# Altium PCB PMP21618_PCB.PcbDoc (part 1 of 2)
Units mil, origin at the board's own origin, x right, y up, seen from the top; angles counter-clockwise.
Board outline 4330 x 1770 mil, 4 copper layers (Top Layer, Signal Layer 1, Signal Layer 2, Bottom Layer), stack 136.834 mil thick; 75 components, 40 nets, 205 pads, 71 vias.
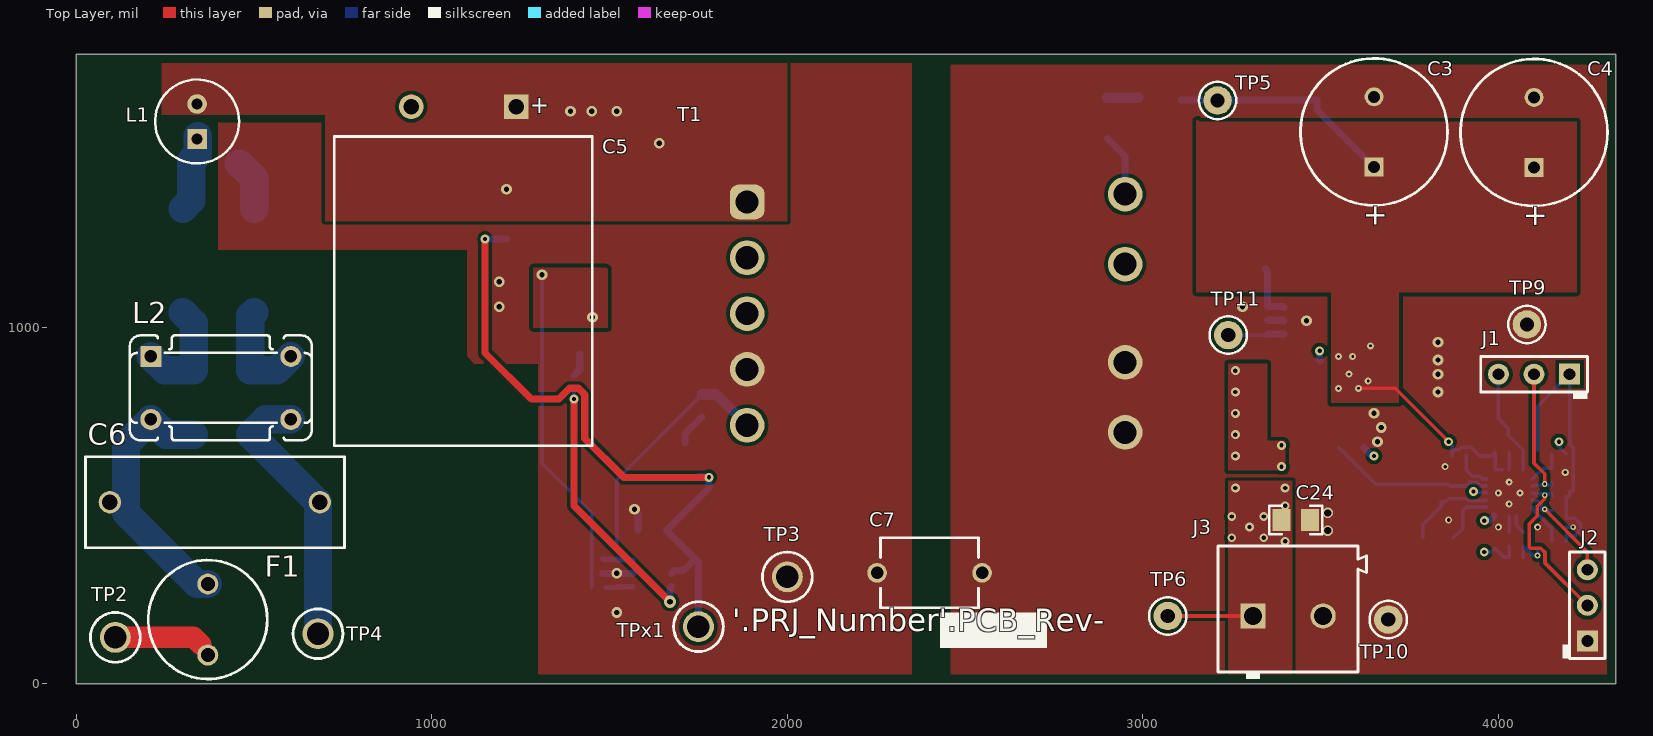
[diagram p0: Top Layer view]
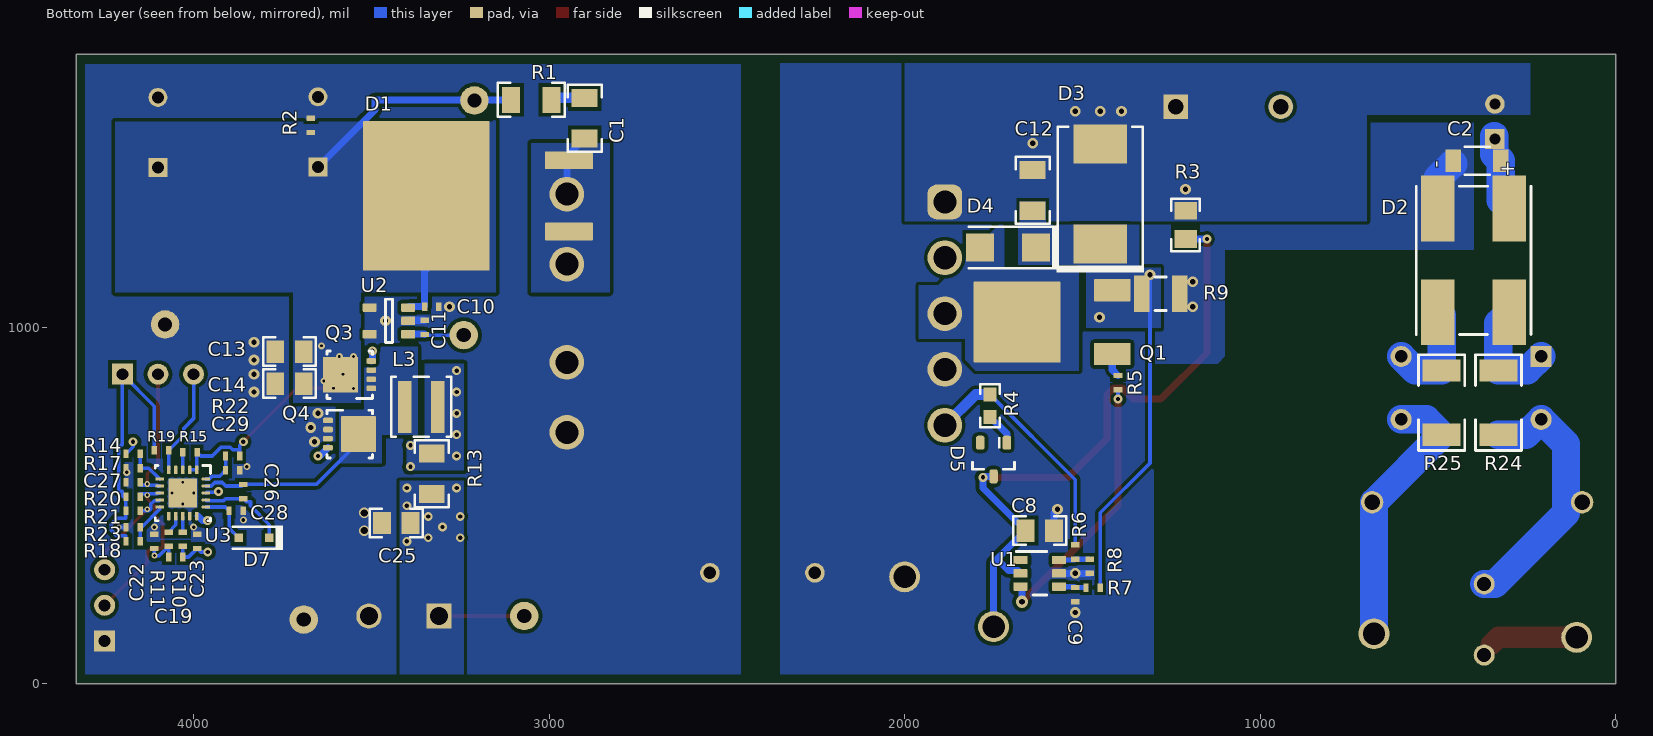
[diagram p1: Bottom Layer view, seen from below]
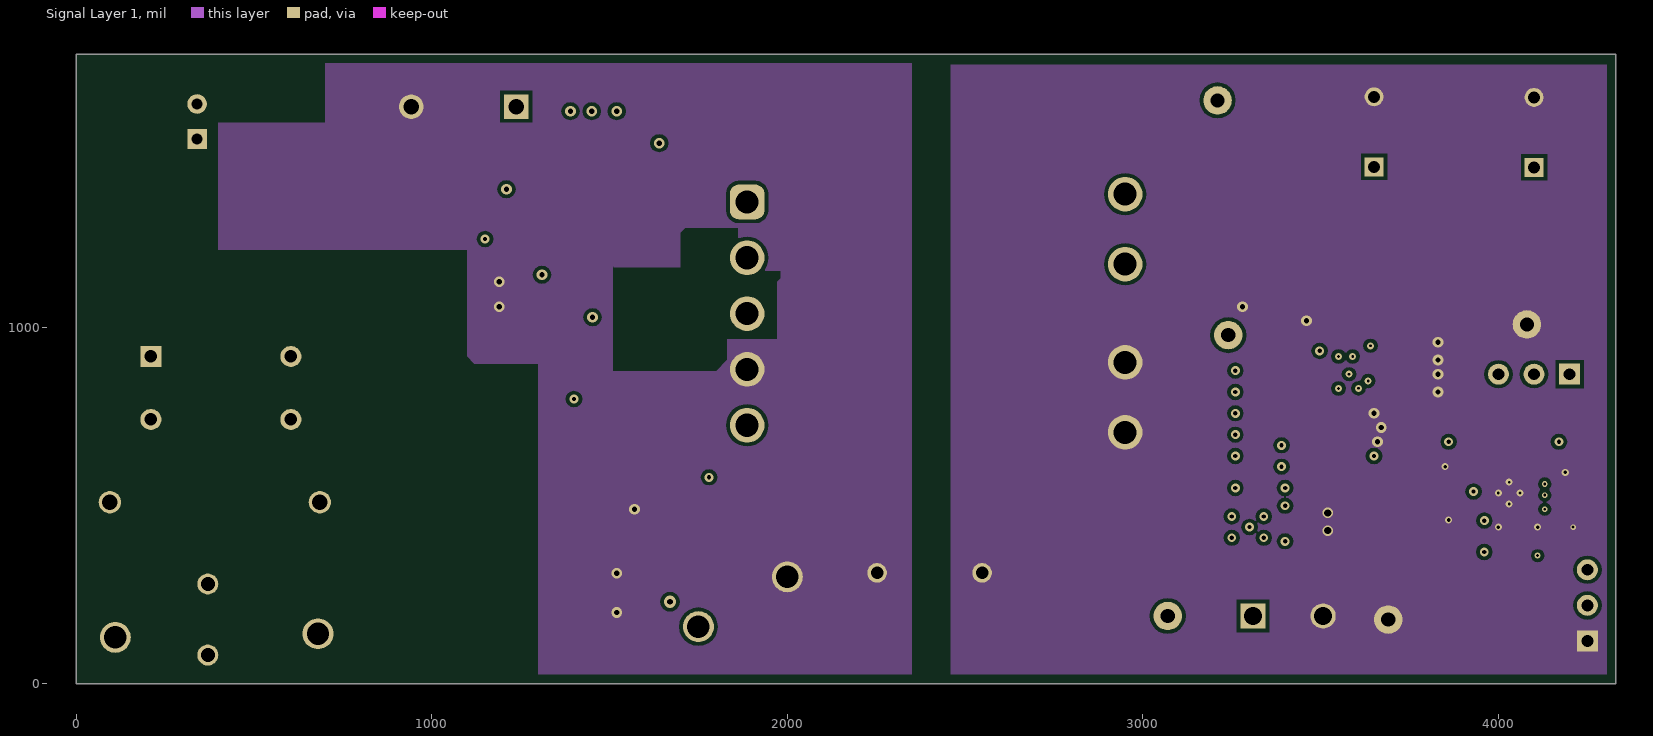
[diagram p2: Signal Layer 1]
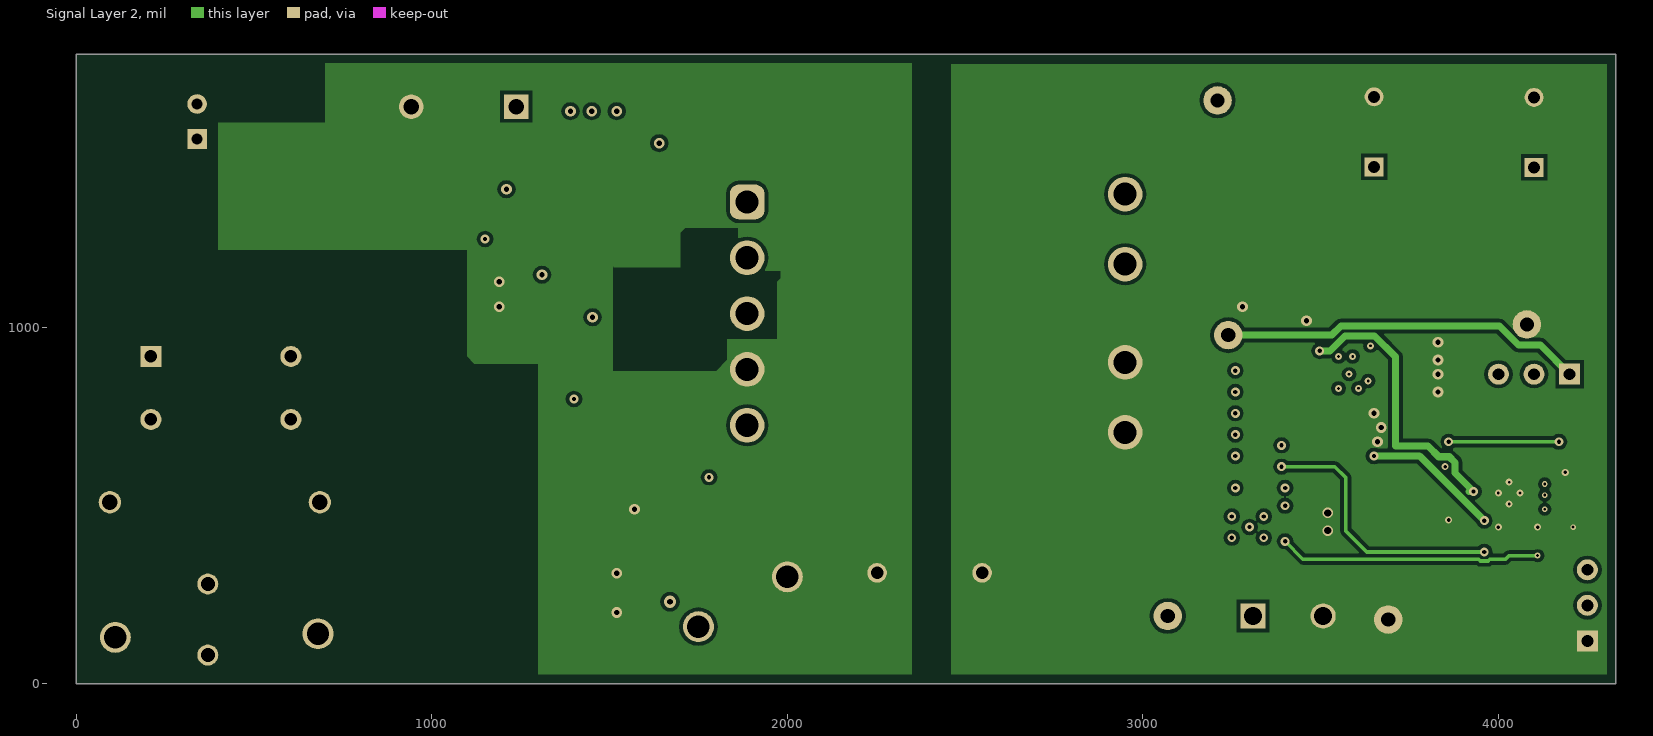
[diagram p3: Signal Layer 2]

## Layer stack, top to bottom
Top Solder: solder mask 0.4, Solder Resist, Dk 3.5
Top Layer: signal copper 2.8
Dielectric1: core 59.2, FR-4, Dk 4.8
Signal Layer 1: signal copper 1.417
Dielectric 3: core 59.2, FR-4, Dk 4.8
Signal Layer 2: signal copper 1.417
Dielectric 2: core 10, FR-4, Dk 4.8
Bottom Layer: signal copper 2.8
Bottom Solder: solder mask 0.4, Solder Resist, Dk 3.5

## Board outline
0,0 4330,0 4330,1770 0,1770

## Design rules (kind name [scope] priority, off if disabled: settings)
AcuteAngle [All] p1: minimum=4.50000000000000E+0001 checktracksonly=FALSE
AssemblyTestPointUsage [All] p1: valid=2
BoardOutlineClearance BoardOutlineClearance_MountingHoles [OnCopper and InComponentClass('Mounting Holes')] p1: gap=40 ignorepadtopadclearanceinfootprint=FALSE
BoardOutlineClearance BoardOutlineClearance_Poly [OnCopper and IsPoly] p2: gap=25 ignorepadtopadclearanceinfootprint=FALSE
BoardOutlineClearance [OnCopper and Not InComponentClass('Logo') and not InComponentClass('FiducialMark') and not InRegion(1000,500,4000,800) and not InPoly] p3: gap=75 ignorepadtopadclearanceinfootprint=FALSE
Clearance Clearance_Keepouts [((IsTrack Or IsArc) And Not InPoly) And IsFree and IsKeepOut vs ((IsTrack Or IsArc) And Not InPoly) And IsFree and IsKeepOut] p1: gap=0 ignorepadtopadclearanceinfootprint=FALSE
Clearance Clearance_Poly [InPolygon] p2: gap=10 ignorepadtopadclearanceinfootprint=FALSE except(0: Arc-Hole Track-Hole SMDPad-Hole THPad-Hole Via-Hole Fill-Hole Poly-Hole Region-Hole Text-Hole)
Clearance Clearance_FiducialMark [IsKeepOut and InComponentClass('FiducialMark') vs IsPad and InComponentClass('FiducialMark')] p3: gap=0 ignorepadtopadclearanceinfootprint=FALSE
Clearance [All] p4: gap=7.87 ignorepadtopadclearanceinfootprint=FALSE except(0: Arc-Hole Track-Hole SMDPad-Hole THPad-Hole Via-Hole Fill-Hole Poly-Hole Region-Hole Text-Hole)
ComponentClearance ComponentClearance_MountingHoles_FiducialMarks [InComponentClass('Mounting Holes') vs InComponentClass('FiducialMark')] p1: gap=50 collisioncheckmode=3 verticalgap=10 showdistances=FALSE
ComponentClearance ComponentClearance_Shunt [InComponentClass('Header') vs InComponentClass('Shunt')] p2: gap=0 collisioncheckmode=3 verticalgap=0 showdistances=FALSE
ComponentClearance ComponentClearance_Logo [InComponentClass('Logo')] p3: gap=50 collisioncheckmode=3 verticalgap=10 showdistances=FALSE
ComponentClearance ComponentClearance_ScrewToNut [(HasFootprint('NY PMS 440 0025 PH')) vs (HasFootprint('Keystone_1902C'))] p4: gap=5 collisioncheckmode=3 verticalgap=10 showdistances=FALSE
ComponentClearance ComponentClearance_MountingHoles [InComponentClass('Mounting Holes')] p5: gap=250 collisioncheckmode=3 verticalgap=100000 showdistances=FALSE
ComponentClearance ComponentClearance_SmallPassives [HasFootprint('0201*') or HasFootprint('0402*') or HasFootprint('0508') or HasFootprint('0603*') or HasFootprint('0612') or HasFootprint('0805*') or HasFootprint('0815*') or HasFootprint('0830*') or HasFootprint('1206*') or HasFootprint('1210*') or HasFootprint('1808*') or HasFootprint('1812*') or HasFootprint('1825*') or HasFootprint('2010*') or HasFootprint('2220*') or HasFootprint('2225*') or HasFootprint('2512*') or HasFootprint('2728*') or HasFootprint('3518*') vs HasFootprint('0201*') or HasFootprint('0402*') or HasFootprint('0508') or HasFootprint('0603*') or HasFootprint('0612') or HasFootprint('0805*') or HasFootprint('0815*') or HasFootprint('0830*') or HasFootprint('1206*') or HasFootprint('1210*') or HasFootprint('1808*') or HasFootprint('1812*') or HasFootprint('1825*') or HasFootprint('2010*') or HasFootprint('2220*') or HasFootprint('2225*') or HasFootprint('2512*') or HasFootprint('2728*') or HasFootprint('3518*')] p6: gap=14.96 collisioncheckmode=3 verticalgap=10 showdistances=FALSE
ComponentClearance ComponentClearance_THtoSMT [IsThruComponent vs IsSMTComponent] p7: gap=40 collisioncheckmode=3 verticalgap=30 showdistances=FALSE
ComponentClearance ComponentClearance_THtoTH [IsThruComponent vs IsThruComponent] p8: gap=30 collisioncheckmode=3 verticalgap=30 showdistances=FALSE
ComponentClearance [All] p9: gap=30 collisioncheckmode=3 verticalgap=10 showdistances=FALSE
DiffPairsRouting [All] p1: maxlimit=100 minlimit=10 mostfreqgap=10 toplayer_minwidth=15 toplayer_maxwidth=15 toplayer_prefwidth=15 midlayer1_minwidth=15 midlayer1_maxwidth=15 midlayer1_prefwidth=15 midlayer2_minwidth=15 midlayer2_maxwidth=15 midlayer2_prefwidth=15 bottomlayer_minwidth=15 bottomlayer_maxwidth=15 bottomlayer_prefwidth=15 maxuncoupledlength=1000
FabricationTestPointUsage TestPointUsage [All] p1: valid=2 allowmultiple=FALSE
FabricationTestpoint Testpoint [All] p1: side=3 testpointundercomponent=TRUE minsize=40 maxsize=100 preferedsize=60 minholesize=0 maxholesize=40 preferedholesize=32 testpointgrid=1 allowsidetop=TRUE allowsidebottom=TRUE usegrid=TRUE gridtolerance=0.01
FanoutControl Fanout_LCC [IsLCC] p1: bgadir=Out bgaviamode=Centered fanoutstyle=Auto fanoutdirection=Alternating viagrid=1 // Fanout_LCC (Default Rule)
FanoutControl Fanout_BGA [IsBGA] p2: bgadir=Out bgaviamode=Centered fanoutstyle=Auto fanoutdirection=Alternating viagrid=1 // Fanout_BGA (Default Rule)
FanoutControl Fanout_Default [All] p4: bgadir=Out bgaviamode=Centered fanoutstyle=Auto fanoutdirection=Alternating viagrid=1 // Fanout_Default (Default Rule)
FanoutControl Fanout_Small [(CompPinCount < 5)] p5: bgadir=Out bgaviamode=Centered fanoutstyle=Auto fanoutdirection=OutThenIn viagrid=1 // Fanout_Small (Default Rule)
HoleSize [All] p1: absolutevalues=TRUE maxlimit=251 minlimit=7.87 maxpercent=80.000 minpercent=20.000
MinimumAnnularRing MinimumAnnularRing_ThermalPadVias [IsVia and InAnyComponent] p1: minimumring=5.91
MinimumAnnularRing [All] p2: minimumring=3.9
MinimumSolderMaskSliver MinimumSolderMaskSliver_Logo [InComponentClass('Logo') vs InComponentClass('Logo')] p1: minsoldermaskwidth=0.7
MinimumSolderMaskSliver [All] p2: minsoldermaskwidth=0
PlaneClearance [All] p1: clearance=10
PlaneConnect [All] p1: planeconnectstyle=Direct reliefexpansion=10 reliefentries=4 reliefconductorwidth=10 reliefairgap=10
PolygonConnect [All] p1: connectstyle=Direct reliefconductorwidth=10 reliefentries=4 polygonreliefangle="90 Angle" airgapwidth=10
RoutingVias ThermalPadVias [IsVia and InAnyComponent] p1: holewidth=7.87 width=19.68 viastyle="Through Hole" minholewidth=7.87 minwidth=19.68 maxholewidth=12.99 maxwidth=23.62
RoutingVias [All] p2: holewidth=16 width=34 viastyle="Through Hole" minholewidth=8 minwidth=16 maxholewidth=40 maxwidth=65
SilkToBoardRegionClearance [Not ((IsComment or IsDesignator) And (Hide <> 'False')) and not InRegion(1000,500,4000,800)] p1:
SilkToSilkClearance SilkToSilkClearance_Pb-FreeLogo [(HasFootprint('Pb-Free_Overlay_Medium') OR HasFootprint('Pb-Free_Overlay_Small')) vs (HasFootprint('Pb-Free_Overlay_Medium') OR HasFootprint('Pb-Free_Overlay_Small'))] p1: silktosilkclearance=0
SilkToSilkClearance [All] p2: silktosilkclearance=4
SilkToSolderMaskClearance SilkToComponentPadClearance [(IsPad or IsFill or IsRegion) and InAnycomponent] p1: minsilkscreentomaskgap=5 clearancetoexposedcopper=TRUE
SilkToSolderMaskClearance "Silk to Solder Mask Opening" [All] p2: minsilkscreentomaskgap=0.1 clearancetoexposedcopper=TRUE
SolderMaskExpansion [All] p1: expansion=1.97
Width [All] p1: maxlimit=100 minlimit=6 preferedwidth=10 checkconnectedcopper=TRUE
14 further rules are at their usual default settings.

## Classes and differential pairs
component class BQ24725Z: C10 C11 C13 C14 C19 C22 C23 C24 C25 C26 C27 C28 C29 D7 J1 J2 J3 L3 Q3 Q4 R10 R11 R13 R14 R15 R17 R18 R19 R20 R21 R22 R23 TP5 TP6 TP9 TP10 TP11 U2 U3
component class Header: J1 J2
component class PMP21618_BlankSheet: C1 C2 C3 C4 C5 C6 C7 C8 C9 C12 D1 D2 D3 D4 D5 F1 L1 L2 Q1 R1 R2 R3 R4 R5 R6 R7 R8 R9 R24 R25 T1 TP2 TP3 TP4 TPx1 U1

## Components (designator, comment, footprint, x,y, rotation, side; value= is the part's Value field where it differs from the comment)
C1 "Capacitor" 1206 2900,1590 r270 bottom value=330pF
C2 "Capacitor" 1206_190 390,1470 r0 bottom value=0.1uF
C3 "Cap_Polarized" Chemi-Con_1000x1600 3650,1551.57 r90 top value=330uF
C4 "Cap_Polarized" Chemi-Con_1000x1600 4100,1550 r90 top value=330uF
C5 "EEU-EE2G470S" EE_1800x2000_HorizontalUp 1090,1150 r180 top value=47uF
C6 "890324025017" WCAP-FTX2_1800x600x1200 390,510 r0 top value=0.1uF
C7 "DE2E3KY152MN3AM02F" KY_700x500x1000 2400,311.49 r180 top value=1500pF
C8 "Capacitor" 0805_HV 1620,430 r180 bottom value=4.7uF
C9 "Capacitor" 0402S 1520,250 r270 bottom value=100pF
C10 "Capacitor" 0402S 3330,1060 r180 bottom value=2.2uF
C11 "Capacitor" 0402S 3350.31,1001.81 r90 bottom value=2.2uF
C12 "Capacitor" 1206 1640,1387.09 r270 bottom value=1000pF
C13 "Capacitor" 0805_HV 3729.99,933.66 r180 bottom value=10uF
C14 "Capacitor" 0805_HV 3729.99,843.66 r180 bottom value=10uF
C19 "Capacitor" 0402S 4050.16,355.91 r180 bottom value=0.1uF
C22 "Capacitor" 0402S 4110,400 r270 bottom value=0.1uF
C23 "Capacitor" 0402S 3990,400 r270 bottom value=0.1uF
C24 "Capacitor" 0805_HV 3430,460 r180 top value=10uF
C25 "Capacitor" 0805_HV 3430,451.49 r180 bottom value=10uF
C26 "Capacitor" 0402S 3860,540 r270 bottom value=0.047uF
C27 "Capacitor" 0402S 4170.16,565.91 r0 bottom value=100pF
C28 "Capacitor" 0402S 3880.16,485.91 r180 bottom value=1uF
C29 "Capacitor" 0402S 3890,600 r180 bottom value=1uF
D1 "MBRB20200CTT4G" DDPAK 3190,1371.49 r0 bottom value=200V
D2 "DIODE_BRIDGE_Pos1_Neg4_AC23" Z4-D 400,1190 r270 bottom value=600V
D3 "Diode_TVS_Uni" SMC 1450,1376.49 r90 bottom value=150V
D4 "DIODE" SMA 1710,1226.49 r0 bottom value=600V
D5 "DIODE_A1C3" SOT-23 1750,630 r270 bottom value=200V
D7 "DIODE_SCHOTTKY" SOD-323 3830,410 r0 bottom value=30V
F1 "Fuse" FUSE_372 370,180 r270 top
J1 "Header_3x1" Mill-Max_800-10-003-10-001000 4100,870 r180 top
J2 "Header_3x1" Mill-Max_800-10-003-10-001000 4250,220 r90 top
J3 "691 101 710 002" Wurth_691101710002 3408.43,190 r0 top
L1 "Inductor_Iron" WE-TI_5075 340,1580.79 r90 top value=22uH
L2 "INDUCTOR_COUPLED_12_43" WE-CMB_XS 406.85,831.42 r0 top value=1mH
L3 "Inductor_Iron" XAL4030 3360,777.99 r180 bottom value=4.7uH
Q1 "IPD60R950C6ATMA1" DPAK 1550,1016.49 r0 bottom value=600V
Q3 "MOSFET_N_D56789G4S123" DNH0008A 3561.02,868.7 r0 bottom value=30V
Q4 "MOSFET_N_D56789G4S123" DNH0008A 3561.02,701.61 r180 bottom value=30V
R1 "Resistor" 1206 3050,1641.49 r0 bottom value=20
R2 "Resistor" 0402S 3670,1570 r270 bottom value=10.0k
R3 "Resistor" 0805_HV 1210,1290 r90 bottom value=1.5Meg
R4 "Resistor" 0603 1760,781.49 r90 bottom value=0
R5 "Resistor" 0402S 1400,846.49 r90 bottom value=0
R6 "Resistor" 0402S 1520,370 r90 bottom value=110k
R7 "Resistor" 0402S 1470,270 r180 bottom value=681
R8 "Resistor" 0402S 1480,330 r90 bottom value=33.2k
R9 "Resistor" 1210L 1280,1096.49 r0 bottom value=0.27
R10 "Resistor" 0402S 4030.16,405.91 r270 bottom value=10
R11 "Resistor" 0402S 4070.16,405.91 r270 bottom value=7.5
R13 "Resistor" 1206 3330,590 r270 bottom value=0.01
R14 "Resistor" 0402S 4170.16,645.91 r0 bottom value=430k
R15 "Resistor" 0402S 4010,650 r180 bottom value=4.02k
R17 "Resistor" 0402S 4170.16,605.91 r180 bottom value=82.5k
R18 "Resistor" 0402S 4170,400 r0 bottom value=316k
R19 "Resistor" 0402S 4090.16,655.91 r180 bottom value=10.0k
R20 "Resistor" 0402S 4170.16,525.91 r180 bottom value=10.0k
R21 "Resistor" 0402S 4170.16,485.91 r180 bottom value=10.0k
R22 "Resistor" 0402S 3890,640 r0 bottom value=10
R23 "Resistor" 0402S 4170,440 r180 bottom value=100k
R24 "Resistor" 2010 330,790 r90 bottom value=0
R25 "Resistor" 2010 490,790 r90 bottom value=0
T1 "RLTI-1298" Renco_RLTI-1298 2410,1041.49 r0 top value=220uH
TP2 "5012" Keystone5012 110,130 r90 top
TP3 "5011" Keystone5011 2000,300 r0 top
TP4 "5012" Keystone5012 680,140 r90 top
TP5 "5000" Keystone5000 3210,1640 r180 top
TP6 "5000" Keystone5000 3070,190 r180 top
TP9 "5001" Keystone5001 4080,1010 r180 top
TP10 "5001" Keystone5001 3690,180 r90 top
TP11 "5000" Keystone5000 3240,980 r90 top
TPx1 "5010" Keystone5010 1750,160 r0 top
U1 "UCC28704DBVR-1" DBV0006A_N 1620,310 r180 bottom
U2 "TI-TLV7013XDBV5" DBV0005A_N 3450.31,1020 r0 bottom
U3 "BQ24725ARGRT" RGR0020A 4030.16,535.91 r270 bottom

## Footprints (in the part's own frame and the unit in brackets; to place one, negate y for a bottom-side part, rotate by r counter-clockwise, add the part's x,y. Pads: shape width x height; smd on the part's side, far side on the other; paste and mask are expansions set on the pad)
0402S [mil] "Based on C0402S footprint from PADS legacy"
  rect 15x24 smd: 1(-20,0) 2(20,0)
  body extent -22,-12 22,12, height 24
0603 [mm] "0603 from SM-752 data"
  rect 1x0.95 smd: 1(-0.8,0) 2(0.8,0)
  silkscreen extent -1.52,-0.69 1.52,0.69, body extent -0.87,-0.47 0.87,0.47, height 1
0805_HV [mil] "0805 with 30mil clearance between pads"
  rect 50x63 smd: 1(-40,0) 2(40,0)
  silkscreen extent -74,-40 74,40, body extent -43,-29 43,29, height 57
1206 [mm] "1206 from SM-752 data"
  rect 1.3x1.85 smd: 1(-1.45,0) 2(1.45,0)
  silkscreen extent -2.4,-1.21 2.4,1.21, body extent -1.7,-0.9 1.7,0.9, height 1.35
1206_190 [mm] "1206_190"
  rect 1.1x1.6 smd: 1(-1.7,0) 2(1.7,0)
  silkscreen extent -0.9,-1 0.9,1, body extent -1.75,-0.95 1.75,0.95, height 1.9
1210L [mm] "1210 from SM-752 data"
  rect 1.1x2.6 smd: 1(-1.35,0) 2(1.35,0)
  silkscreen extent -0.4,-1.2 0.4,1.2, body extent -1.7,-1.35 1.7,1.35, height 1.35
2010 [mm] "Chip Capacitor, Body 5.08x2.54mm, IPC Medium Density"
  rect 1.6x2.7 smd: 1(-2.3,0) 2(2.3,0)
  silkscreen extent -3.42,-1.65 3.42,1.65, body extent -2.73,-1.45 2.73,1.45, height 1.66
Chemi-Con_1000x1600 [mm] "TH, 2-Leads, Dia 10mm, Pin Spacing 5mm"
  rect 1.35x1.35 hole 0.85: 1(-2.5,0)
  round 1.35 hole 0.85: 2(2.5,0)
  silkscreen extent -5.25,-5.25 5.25,5.25, body extent -5.25,-5.25 5.26,5.25, height 17.5
DBV0005A_N [mm] "SOT23, 5-Leads, Body 2.9x1.6mm, Pitch 0.95mm, Lead Span 2.8mm, IPC Medium Density"
  rrect17% 1x0.6 smd: 1(-1.375,0.95) 2(-1.375,0) 3(-1.375,-0.95) 4(1.375,-0.95) 5(1.375,0.95)
  silkscreen extent -0.25,-1.55 0.25,1.55, body extent -1.42,-1.46 1.42,1.46, height 1.09
DBV0006A_N [mm] "SOT23, 6-Leads, Body 2.9x1.6mm, Pitch 0.95mm, Lead Span 2.8mm, IPC Medium Density"
  rrect17% 1x0.6 smd: 1(-1.375,0.95) 2(-1.375,0) 3(-1.375,-0.95) 4(1.375,-0.95) 5(1.375,0) 6(1.375,0.95)
  silkscreen extent -1.68,-1.55 0.5,1.55, body extent -1.42,-1.46 1.42,1.46, height 1.12
DDPAK [mil] "D2-PAK, 3-Pads, Body 9.7x10.4mm (max), TO-263AB, using Vishay Silionix recommended pad sizes"
  rrect8% 135x49.49 smd: 1(-246.06,100) 3(-246.06,-100)
  rrect1% 355x420 smd paste-181.1: 2(155.51,0)
  body extent -295,-202 324,202, height 180
DNH0008A [mm] "VSONP-8"
  rrect50% 0.7x0.4 smd paste-0.05 mask-0.05: 1(-1.55,0.975) 2(-1.55,0.325) 3(-1.55,-0.325) 4(-1.55,-0.975) 5(1.55,-0.975) 6(1.55,-0.325) 7(1.55,0.325) 8(1.55,0.975)
  rrect4% 2.51x2.55 smd paste-1.5 mask-1.5: 9(0.645,0)
  rrect14% 0.705x1.125 on Bottom Paste: 9A(-0.208,0.662) 9B(0.697,0.662) 9C(-0.208,-0.663) 9D(0.697,-0.663)
  silkscreen extent -1.62,-1.7 1.62,1.7, body extent -1.65,-1.65 1.65,1.65, height 0.91
DPAK [mm] "D-PAK, 3-Pads, Body 6.22x6.73mm (max), TO-252AA using nominal STEP model"
  rrect6% 2.6x1.6 smd: 1(-3.4,2.28) 3(-3.4,-2.28)
  rrect2% 6.2x5.8 smd paste-3: 2(3.4,0)
  body extent -3.86,-3.29 5.84,3.29, height 2.48
EE_1800x2000_HorizontalUp [mm] "PANASONIC"
  rect 1.75x1.75 hole 1.1: 1(-3.75,-12)
  round 1.75 hole 1.1: 2(3.75,-12)
  silkscreen extent -9.17,-9.88 9.25,12.22, body extent -9.2,-12.42 9.2,12.22, height 18.48
FUSE_372 [mm] "LITTELFUSE"
  round 1.5 hole 1: 1(-2.54,0) 2(2.54,0)
  silkscreen extent -4.25,-4.25 4.25,4.25, body extent -4.25,-4.25 4.25,4.25, height 8
Keystone5000 [mil] "For Keystone 500x miniature loop terminals"
  round 80 hole 40: 1(0,0)
  silkscreen extent -52,-52 52,52, body extent -49,-49 49,49, height 182
Keystone5001 [mil] "For Keystone 500x miniature loop terminals"
  round 80 hole 40: 1(0,0)
  silkscreen extent -52,-52 52,52, body extent -49,-49 49,49, height 182
Keystone5010 [mil] "Keystone Multipurpose loops"
  round 87 hole 63: 1(0,0)
  silkscreen extent -70,-70 70,70, body extent -63,-63 63,62, height 319
Keystone5011 [mil] "Keystone Multipurpose loops"
  round 87 hole 63: 1(0,0)
  silkscreen extent -70,-70 70,70, body extent -63,-63 63,62, height 319
Keystone5012 [mil] "Keystone Multipurpose loops"
  round 87 hole 63: 1(0,0)
  silkscreen extent -70,-70 70,70, body extent -63,-63 63,62, height 319
KY_700x500x1000 [mm] "TH, 2- Leads, Body 7x5mm, Pin Spacing 7.5mm"
  round 1.4 hole 0.9: 1(-3.75,0) 2(3.75,0)
  silkscreen extent -3.5,-2.5 3.5,2.5, body extent -4.05,-2.5 4.05,2.5, height 9.97
Mill-Max_800-10-003-10-001000 [mm] "Mill-Max"
  rect 1.5x1.5 hole 0.85: 1(-2.54,0)
  round 1.5 hole 0.85: 2(0,0) 3(2.54,0)
  silkscreen extent -3.81,-1.27 3.81,1.78, body extent -3.81,-1.27 3.81,1.27, height 8.13
Renco_RLTI-1298 [mm] "TH, 9-Leads, Body 1400x1200mil"
  rrect50% 2.475x2.475 hole 1.65: 1(-13.284,7.95)
  round 2.475 hole 1.65: 2(-13.284,3.962) 3(-13.284,-0.025) 4(-13.284,-4.013) 5(-13.284,-8.001) 6(13.716,-8.509) 7(13.716,-3.505) 8(13.716,3.505) 9(13.716,8.509)
  body extent -14.93,-13.05 17.97,12.95, height 18.01
RGR0020A [mm] "QFN, 20-Leads, Body 3.5x3.5mm, Pitch 0.5mm, Thermal Pad 2.05x2.05mm, TI Recommended"
  rrect42% 0.6x0.24 smd: 1(-1.65,1) 2(-1.65,0.5) 3(-1.65,0) 4(-1.65,-0.5) 5(-1.65,-1) 11(1.65,-1) 12(1.65,-0.5) 13(1.65,0) 14(1.65,0.5) 15(1.65,1)
  rrect42% 0.24x0.6 smd: 6(-1,-1.65) 7(-0.5,-1.65) 8(0,-1.65) 9(0.5,-1.65) 10(1,-1.65) 16(1,1.65) 17(0.5,1.65) 18(0,1.65) 19(-0.5,1.65) 20(-1,1.65)
  rrect5% 2.05x2.05 smd paste-1.025: 21(0,0)
  silkscreen extent -1.97,-1.97 1.97,1.97, body extent -1.75,-1.75 1.75,1.75, height 1
SMA [mm] "Molded Diode, 2-Leads, Body 4.3x2.6mm, IPC Medium Density, based on OnSemi component dimensions and land pattern"
  rect 2x2 smd: 1(-2,0) 2(2,0)
  silkscreen extent -3.66,-1.57 2.79,1.57, body extent -2.6,-1.3 2.6,1.3, height 2.42
SMC [mil] "Molded Diode, 2-Leads, Body 6.9x5.8mm, IPC Medium Density, based on OnSemi component dimensions and land patterns"
  rect 110x150 smd: 1(-140.49,0) 2(140.49,0)
  silkscreen extent -221,-123 189,124, body extent -156,-116 156,116, height 91
SOD-323 [mm] "NXP recommended land pattern"
  rect 0.6x0.6 smd paste-0.05: 1(-1.1,0) 2(1.1,0)
  silkscreen extent -2.06,-0.86 1.53,0.86, body extent -1.3,-0.67 1.3,0.68, height 1.1
SOT-23 [mm] "SOT23, 3-Leads, Body 2.9x1.3mm, Pitch 0.95mm, Lead Span 2.5mm, IPC Medium Density"
  rrect50% 1x0.6 smd: 1(-1.2,0.95) 2(-1.2,-0.95) 3(1.2,0)
  silkscreen extent -1.63,-1.5 0.7,1.5, body extent -1.16,-1.45 1.21,1.45, height 1
WCAP-FTX2_1800x600x1200 [mm] "TH, 2-Leads, Body 18x6mm, Lead Spacing 15mm"
  round 1.6 hole 1.1: 1(-7.5,0) 2(7.5,0)
  silkscreen extent -9.25,-3.25 9.25,3.25, body extent -9.25,-3.25 9.25,3.25, height 12.5
WE-CMB_XS [mm] "WE-CMB Series Size XS"
  rect 1.5x1.5 hole 0.9: 1(-5,2.25)
  round 1.5 hole 0.9: 2(-5,-2.25) 3(5,-2.25) 4(5,2.25)
  silkscreen extent -6.5,-3.75 6.5,3.75, body extent -6.5,-3.75 6.5,3.75, height 16.24
WE-TI_5075 [mm] "Wurth WE-TI 5075"
  rect 1.4x1.4 hole 0.787: 1(-1.25,0)
  round 1.4 hole 0.787: 2(1.25,0)
  silkscreen extent -3,-3 3,3, body extent -3,-3 3,3, height 8.5
Wurth_691101710002 [mm] "Terminal Block, 5 mm, 2x1, TH"
  rect 1.8x1.8 hole 1.3: 1(-2.5,0)
  round 1.8 hole 1.3: 2(2.5,0)
  silkscreen extent -5,-4.5 5.6,5, body extent -5.6,-4 5.6,5, height 12.5
XAL4030 [mil] "Coilcraft XAL4030 7/18/12"
  rect 38x146 smd: 1(-46.5,0) 2(46.5,0)
  silkscreen extent -85,-85 85,85, body extent -84,-84 84,84, height 122
Z4-D [mm] "SMD, 4-Leads, Body 8.1x10.5mm"
  rect 4.7x2.4 smd: 1(-3.7,2.55) 2(3.7,2.55) 3(3.7,-2.55) 4(-3.7,-2.55)
  silkscreen extent -5.3,-4.1 5.3,4.1, body extent -5.3,-4.1 5.3,4.1, height 1.56

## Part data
C1: library part CMP-0008887-2, "CAP, CERM, 330 pF, 630 V, +/- 5%, C0G/NP0, 1206", Cap_Case=1206, Manufacturer=MuRata, PartNumber=GRM31A5C2J331JW01D, Supplier Part Number 1=490-5276-1-ND, TempCo=C0G/NP0, Tolerance_%=5%, Value1=Unknown, Value2=630V, ValueDisplayed=330pF
C2: library part CMP-0008727-2, "CAP, CERM, 0.1 uF, 450 V, +/- 10%, X7T, 1206_190", Cap_Case=1206, Manufacturer=TDK, PartNumber=C3216X7T2W104K160AA, Supplier Part Number 1=445-7758-1-ND, TempCo=X7T, Tolerance_%=10%, Value1=Unknown, Value2=450V, ValueDisplayed=0.1uF
C3 C4: library part CMP-0010424-2, "CAP, AL, 330 uF, 35 V, +/- 20%, TH", Cap_Case=10x16, Manufacturer=Chemi-Con, PartNumber=EKZE350ELL331MJ16S, Supplier Part Number 1=565-1693-ND, Tolerance_%=20%, Value1=Unknown, Value2=35V, ValueDisplayed=330uF
C5: library part CMP-0010026-3, "CAP, AL, 47 uF, 400 V, +/- 20%, TH", Cap_Case=18x20, Manufacturer=Panasonic, Supplier Part Number 1=P13667-ND, Tolerance_%=20%, Value1=Unknown, Value2=400V, ValueDisplayed=47uF
C6: library part CMP-0012314-3, "CAP, Film, 0.1 uF, 275 V, +/- 10%, TH", Cap_Case=18x6x12mm, Manufacturer="Wurth Elektronik", Supplier Part Number 1=732-5898-ND, Tolerance_%=10%, Value1=Unknown, Value2=275V, ValueDisplayed=0.1uF
C7: library part CMP-0009609-4, "CAP, CERM, 1500 pF, X1 250 VAC/Y2 300 VAC, +/- 20%, E, TH", Cap_Case=7x5x10mm, Manufacturer=MuRata, Supplier Part Number 1=490-9553-1-ND, TempCo=E, Tolerance_%=20%, Value1=Unknown, ValueDisplayed=1500pF
C8: library part CMP-0007885-2, "CAP, CERM, 4.7 uF, 35 V, +/- 10%, X7R, 0805", Cap_Case=0805, Manufacturer=TDK, PartNumber=C2012X7R1V475K125AC, Supplier Part Number 1=445-7555-1-ND, TempCo=X7R, Tolerance_%=10%, Value1="0.002346 ohm", Value2=35V, ValueDisplayed=4.7uF
C9: library part CMP-0006410-2, "CAP, CERM, 100 pF, 50 V, +/- 5%, C0G/NP0, 0402", Cap_Case=0402, Manufacturer=MuRata, PartNumber=GRM1555C1H101JA01D, Supplier Part Number 1=81-GRM1555C1H101JA1D, TempCo=C0G/NP0, Tolerance_%=5%, Value1=Unknown, Value2=50V, ValueDisplayed=100pF
C10 C11: library part CMP-0006594-2, "CAP, CERM, 2.2 uF, 16 V, +/- 10%, X5R, 0402", Cap_Case=0402, Manufacturer=MuRata, PartNumber=GRM155R61C225KE11D, Supplier Part Number 1=490-10695-1-ND, TempCo=X5R, Tolerance_%=10%, Value1=Unknown, Value2=16V, ValueDisplayed=2.2uF
C12: library part CMP-0008909-2, "CAP, CERM, 1000 pF, 630 V, +/- 10%, X7R, 1206", Cap_Case=1206, Manufacturer=MuRata, PartNumber=GRM31BR72J102KW01L, Supplier Part Number 1=490-3506-1-ND, TempCo=X7R, Tolerance_%=10%, Value1=Unknown, Value2=630V, ValueDisplayed=1000pF
C13 C14 C24 C25: library part CMP-0008414-2, "CAP, CERM, 10 uF, 25 V, +/- 10%, X5R, 0805", Cap_Case=0805, Manufacturer="Taiyo Yuden", PartNumber=TMK212BBJ106KG-T, Supplier Part Number 1=587-2985-1-ND, TempCo=X5R, Tolerance_%=10%, Value1=Unknown, Value2=25V, ValueDisplayed=10uF
C19 C22 C23: library part CMP-0006289-2, "CAP, CERM, 0.1 uF, 50 V, +/- 10%, X6S, 0402", Cap_Case=0402, Manufacturer=TDK, PartNumber=C1005X6S1H104K050BB, Supplier Part Number 1=445-7356-1-ND, TempCo=X6S, Tolerance_%=10%, Value1="0.039064 ohm", Value2=50V, ValueDisplayed=0.1uF
C26: library part CMP-0006669-2, "CAP, CERM, 0.047 uF, 25 V, +/- 10%, X7R, 0402", Cap_Case=0402, Manufacturer=MuRata, PartNumber=GRM155R71E473KA88D, Supplier Part Number 1=490-3254-1-ND, TempCo=X7R, Tolerance_%=10%, Value1=Unknown, Value2=25V, ValueDisplayed=0.047uF
C27: library part CMP-0006233-2, "CAP, CERM, 100 pF, 25 V, +/- 5%, C0G/NP0, 0402", Cap_Case=0402, Manufacturer=Kemet, PartNumber=C0402C101J3GACTU, Supplier Part Number 1=399-1022-1-ND, TempCo=C0G/NP0, Tolerance_%=5%, Value1=Unknown, Value2=25V, ValueDisplayed=100pF
C28 C29: library part CMP-0006608-2, "CAP, CERM, 1 uF, 25 V, +/- 10%, X5R, 0402", Cap_Case=0402, Manufacturer=MuRata, PartNumber=GRM155R61E105KA12D, Supplier Part Number 1=490-10017-1-ND, TempCo=X5R, Tolerance_%=10%, Value1=Unknown, Value2=25V, ValueDisplayed=1uF
D1: library part CMP-0028500-3, "Diode, Schottky, 200 V, 20 A, DDPAK", Manufacturer="ON Semiconductor", Value1=20A, Value2=1V
D2: library part CMP-0029244-3, "Diode, P-N-Bridge, 600 V, 4 A, Z4-D", Manufacturer="Comchip Technology", PartNumber=Z4DGP406L-HF, Value1=4A, Value2=0.95V
D3: library part CMP-0005708-2, "Diode, TVS, Uni, 150 V, 243 Vc, SMC", Manufacturer="Micro Commercial Components", PartNumber=SMCJ150A-TP, Supplier Part Number 1=SMCJ150A-TPMSCT-ND, Value1=W
D4: library part CMP-0029033-2, "Diode, Ultrafast, 600 V, 1 A, AEC-Q101, SMA", Manufacturer="ON Semiconductor", PartNumber=MURA160T3G, Value1=1A, Value2=1.05V
D5: library part CMP-0076901-2, "Diode, Switching, 200 V, 0.2 A, SOT-23", Manufacturer="Diodes Inc.", PartNumber=BAS21-7-F, Value1=0.2A, Value2=1.25V
D7: library part CMP-0028455-2, "Diode, Schottky, 30 V, 0.2 A, SOD-323", Manufacturer="ON Semiconductor", PartNumber=BAT54HT1G, Value1=0.2A, Value2=0.35V
F1: library part CMP-0003553-2, "Fuse, 1.25 A, 250VAC/VDC, TH", Irating_A=1.25A, Manufacturer=Littelfuse, PartNumber=37211250001, Supplier Part Number 1=WK4250CT-ND
J1 J2: library part CMP-0055086-1, "Header, 100mil, 3x1, TH", Manufacturer=Mill-Max, PartNumber=800-10-003-10-001000, Supplier Part Number 1=ED7203-ND
J3: library part CMP-0054828-1, "Terminal Block, 5 mm, 2x1, Tin, TH", Manufacturer="Wurth Elektronik", Supplier Part Number 1=732-2026-ND
L1: library part CMP-0064517-2, "Inductor, Unshielded Drum Core, Ferrite, 22 uH, 1.7 A, 0.102 ohm, TH", Manufacturer="Wurth Elektronik", PartNumber=7447462220, Supplier Part Number 1=732-2570-ND, Value1="0.102 ohm", Value2=1.7A, ValueDisplayed=22uH
L2: library part CMP-0013113-2, "Coupled inductor, 1 mH, 2 A, 0.045 ohm, TH", Manufacturer="Wurth Elektronik", PartNumber=744821201, Supplier Part Number 1=732-1435-ND, ValueDisplayed=1mH
L3: library part CMP-0060990-1, "Inductor, Shielded, Composite, 4.7 uH, 4.5 A, 0.0401 ohm, SMD", Manufacturer=Coilcraft, PartNumber=XAL4030-472MEB, Supplier Part Number 1=994-XAL4030-472MEB, Value1="0.0401 ohm", Value2=4.5A, ValueDisplayed=4.7uH
Q1: library part CMP-0067579-2, "MOSFET, N-CH, 600 V, 4.4 A, DPAK", Alternate Manufacturer=None, Manufacturer="Infineon Technologies", Supplier Part Number 1=IPD60R950C6ATMA1CT-ND, Value1="? ohm", Value2="13 nC"
Q3 Q4: library part CMP-0000591-2, "MOSFET, N-CH, 30 V, 14 A, DNH0008A (VSONP-8)", Alternate Manufacturer=None, Manufacturer="Texas Instruments", PartNumber=CSD17578Q3A, Supplier Part Number 1=CSD17578Q3A-ND, Value1=0.008, Value2="7.9 nC"
R1: library part CMP-0018627-3, "RES, 20, 5%, 0.25 W, AEC-Q200 Grade 0, 1206", Manufacturer=Vishay-Dale, PartNumber=CRCW120620R0JNEA, Power_W=250mW, Supplier Part Number 1=541-20ECT-ND, TempCo="200 ppm/C", Tolerance_%=5%, Value2=0.25W, Value_Code=20R0, ValueDisplayed=20
R2: library part CMP-0025958-3, "RES, 10.0 k, 1%, 0.063 W, AEC-Q200 Grade 0, 0402", Manufacturer=Vishay-Dale, PartNumber=CRCW040210K0FKED, Power_W=63mW, Supplier Part Number 1=541-10.0KLCT-ND, TempCo="100 ppm/C", Tolerance_%=1%, Value2=0.063W, Value_Code=10k0, ValueDisplayed=10.0k
R3: library part CMP-0020484-3, "RES, 1.5 M, 5%, 0.125 W, AEC-Q200 Grade 0, 0805", Manufacturer=Vishay-Dale, PartNumber=CRCW08051M50JNEA, Power_W=125mW, Supplier Part Number 1=541-1.5MACT-ND, TempCo="200 ppm/C", Tolerance_%=5%, Value2=0.125W, Value_Code=1M50, ValueDisplayed=1.5M
R4: library part CMP-0025697-4, "RES, 0, 5%, 0.1 W, AEC-Q200 Grade 0, 0603", Manufacturer=Vishay-Dale, PartNumber=CRCW06030000Z0EA, Power_W=100mW, Supplier Part Number 1=541-0.0GCT-ND, TempCo="200 ppm/C", Tolerance_%=5%, Value2=0.1W, Value_Code=0000, ValueDisplayed=0
R5: library part CMP-0026822-3, "RES, 0, 5%, 0.063 W, AEC-Q200 Grade 0, 0402", Manufacturer=Vishay-Dale, PartNumber=CRCW04020000Z0ED, Power_W=63mW, Supplier Part Number 1=541-0.0JCT-ND, TempCo="200 ppm/C", Tolerance_%=5%, Value2=0.063W, Value_Code=0000, ValueDisplayed=0
R6: library part CMP-0026828-2, "RES, 110 k, 5%, 0.063 W, AEC-Q200 Grade 0, 0402", Manufacturer=Vishay-Dale, PartNumber=CRCW0402110KJNED, Power_W=63mW, Supplier Part Number 1=541-110KJCT-ND, TempCo="200 ppm/C", Tolerance_%=5%, Value2=0.063W, Value_Code=110k
R7: library part CMP-0026505-2, "RES, 681, 1%, 0.063 W, AEC-Q200 Grade 0, 0402", Manufacturer=Vishay-Dale, PartNumber=CRCW0402681RFKED, Power_W=63mW, Supplier Part Number 1=541-681LCT-ND, TempCo="100 ppm/C", Tolerance_%=1%, Value2=0.063W, Value_Code=681R, ValueDisplayed=681
R8: library part CMP-0026298-2, "RES, 33.2 k, 1%, 0.063 W, AEC-Q200 Grade 0, 0402", Manufacturer=Vishay-Dale, PartNumber=CRCW040233K2FKED, Power_W=63mW, Supplier Part Number 1=541-33.2KLCT-ND, TempCo="100 ppm/C", Tolerance_%=1%, Value2=0.063W, Value_Code=33k2, ValueDisplayed=33.2k
R9: library part CMP-0015177-2, "RES, 0.27, 1%, 0.5 W, 1210", Manufacturer=Rohm, PartNumber=MCR25JZHFLR270, Power_W=500mW, Supplier Part Number 1=RHM.27SCT-ND, TempCo="200 ppm/C", Tolerance_%=1%, Value2=0.5W, Value_Code=R270, ValueDisplayed=0.27
R10 R22: library part CMP-0026827-3, "RES, 10, 5%, 0.063 W, AEC-Q200 Grade 0, 0402", Manufacturer=Vishay-Dale, PartNumber=CRCW040210R0JNED, Power_W=63mW, Supplier Part Number 1=541-10JCT-ND, TempCo="200 ppm/C", Tolerance_%=5%, Value2=0.063W, Value_Code=10R0, ValueDisplayed=10
R11: library part CMP-0026977-3, "RES, 7.5, 5%, 0.063 W, AEC-Q200 Grade 0, 0402", Manufacturer=Vishay-Dale, PartNumber=CRCW04027R50JNED, Power_W=63mW, Supplier Part Number 1=541-7.5JCT-ND, TempCo="200 ppm/C", Tolerance_%=5%, Value2=0.063W, Value_Code=7R50, ValueDisplayed=7.5
R13: library part CMP-0018570-2, "RES, 0.01, 1%, 1 W, 1206", Manufacturer=Vishay-Dale, PartNumber=WSLP1206R0100FEA, Power_W=1W, Supplier Part Number 1=WSLP-.01CT-ND, TempCo="75 ppm/C", Tolerance_%=1%, Value_Code=R010, ValueDisplayed=0.01
R14: library part CMP-0026929-2, "RES, 430 k, 5%, 0.063 W, AEC-Q200 Grade 0, 0402", Manufacturer=Vishay-Dale, PartNumber=CRCW0402430KJNED, Power_W=63mW, Supplier Part Number 1=541-430KJCT-ND, TempCo="200 ppm/C", Tolerance_%=5%, Value2=0.063W, Value_Code=430k
R15: library part CMP-0026405-2, "RES, 4.02 k, 1%, 0.063 W, AEC-Q200 Grade 0, 0402", Manufacturer=Vishay-Dale, PartNumber=CRCW04024K02FKED, Power_W=63mW, Supplier Part Number 1=541-4.02KLCT-ND, TempCo="100 ppm/C", Tolerance_%=1%, Value2=0.063W, Value_Code=4k02, ValueDisplayed=4.02k
R17: library part CMP-0026574-2, "RES, 82.5 k, 1%, 0.063 W, AEC-Q200 Grade 0, 0402", Manufacturer=Vishay-Dale, PartNumber=CRCW040282K5FKED, Power_W=63mW, Supplier Part Number 1=541-82.5KLCT-ND, TempCo="100 ppm/C", Tolerance_%=1%, Value2=0.063W, Value_Code=82k5, ValueDisplayed=82.5k
R18: library part CMP-0026288-2, "RES, 316 k, 1%, 0.063 W, AEC-Q200 Grade 0, 0402", Manufacturer=Vishay-Dale, PartNumber=CRCW0402316KFKED, Power_W=63mW, Supplier Part Number 1=541-316KLCT-ND, TempCo="100 ppm/C", Tolerance_%=1%, Value2=0.063W, Value_Code=316k
R19 R20 R21: library part CMP-0026769-2, "RES, 10.0 k, 0.5%, 0.063 W, AEC-Q200 Grade 0, 0402", Manufacturer=Vishay-Dale, PartNumber=CRCW040210K0DHEDP, Power_W=63mW, Supplier Part Number 1=541-10KAVCT-ND, TempCo="50 ppm/C", Tolerance_%=0.5%, Value2=0.063W, Value_Code=10k0, ValueDisplayed=10.0k
R23: library part CMP-0025950-3, "RES, 100 k, 1%, 0.063 W, AEC-Q200 Grade 0, 0402", Manufacturer=Vishay-Dale, PartNumber=CRCW0402100KFKED, Power_W=63mW, Supplier Part Number 1=541-100KLCT-ND, TempCo="100 ppm/C", Tolerance_%=1%, Value2=0.063W, Value_Code=100k
R24 R25: library part CMP-0016044-3, "RES, 0, 5%, 0.75 W, AEC-Q200 Grade 0, 2010", Manufacturer=Vishay-Dale, PartNumber=CRCW20100000Z0EF, Power_W=750mW, Supplier Part Number 1=541-0.0WCT-ND, TempCo=ppm/C, Tolerance_%=5%, Value2=0.75W, Value_Code=0000, ValueDisplayed=0
T1: library part CMP-0084219-2, "Transformer, 220 uH, TH", Manufacturer="Renco Electronics", ValueDisplayed=220µH
TP2 TP4: library part CMP-0055149-1, "Test Point, Multipurpose, White, TH", Color=White, Manufacturer=Keystone, Supplier Part Number 1=36-5012-ND
TP3: library part CMP-0055148-1, "Test Point, Multipurpose, Black, TH", Color=Black, Manufacturer=Keystone, Supplier Part Number 1=36-5011-ND
TP5 TP6 TP11: library part CMP-0055137-1, "Test Point, Miniature, Red, TH", Color=Red, Manufacturer=Keystone, Supplier Part Number 1=36-5000-ND
TP9 TP10: library part CMP-0055138-1, "Test Point, Miniature, Black, TH", Color=Black, Manufacturer=Keystone, Supplier Part Number 1=36-5001-ND
TPx1: library part CMP-0055147-1, "Test Point, Multipurpose, Red, TH", Color=Red, Manufacturer=Keystone, Supplier Part Number 1=36-5010-ND
U1: library part CMP-0074087-1, "Off-Line Constant-Voltage Constant-Current Flyback Controller With Primary-Side Regulation (PSR), DBV0006A (SOT-23-6)", Alternate Manufacturer="Texas Instruments", Alternate PartNumber=UCC28704DBVT-1
U2: library part CMP-0035538-1, "Single Output LDO, 150 mA, Fixed 3.3 V Output, 2.5 to 24 V Input, with Ultra-Low IQ, 5-pin SOT-23 (DBV), -40 to 85 degC, Green (RoHS & no Sb/Br)", Manufacturer="Texas Instruments", PartNumber=TLV70133DBVR
U3: library part CMP-0034195-2, "1-4 Cell Li+ Battery SMBus Charge Controller with N-Channel Power MOSFET Selector, RGR0020A (VQFN-20)", Alternate Manufacturer="Texas Instruments", Alternate PartNumber=BQ24725ARGRR

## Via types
v1: diameter 25, hole 12, Top Layer to Bottom Layer, 26 vias
v2: diameter 30, hole 15, Top Layer to Bottom Layer, 21 vias
v3: diameter 19.68, hole 7.87, Top Layer to Bottom Layer, 10 vias
v4: diameter 16, hole 8, Top Layer to Bottom Layer, 5 vias
v5: diameter 20, hole 10, Top Layer to Bottom Layer, 5 vias
v6: diameter 30, hole 20, Top Layer to Bottom Layer, 2 vias
v7: diameter 34, hole 16, Top Layer to Bottom Layer, 1 vias
v8: diameter 19.68, hole 7.87, Top Layer to Bottom Layer, tented both sides, 1 vias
